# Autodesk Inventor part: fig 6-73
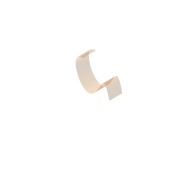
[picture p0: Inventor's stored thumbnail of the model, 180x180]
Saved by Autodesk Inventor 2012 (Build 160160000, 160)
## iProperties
Shininess: 64.0
Length Units: 11269
Angle Units: 11279
Time Units: 11290
Mass Units: 11283
Length Display Precision: 3
Angle Display Precision: 2
Compacted: True
Part Number: fig 6-73
Document SubType Name: Modeling
Created: 2002-12
Designer: deepak
Density: 1 g/cm^3
Material: Default
Density: 0.0
Volumn: 0.0
Area: 0.0
PropertySet Name: Model Information
Control State: 0
Master: False
Checked Out: False
Author: deepak
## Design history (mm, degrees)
sketch "Sketch1"
  geometry: 5 further points
  constraints: 5 other
extrude_surface "ExtrusionSrf1" sketch "Sketch1" dims "d0" = 20, "d1" = 0
body "Srf1"
